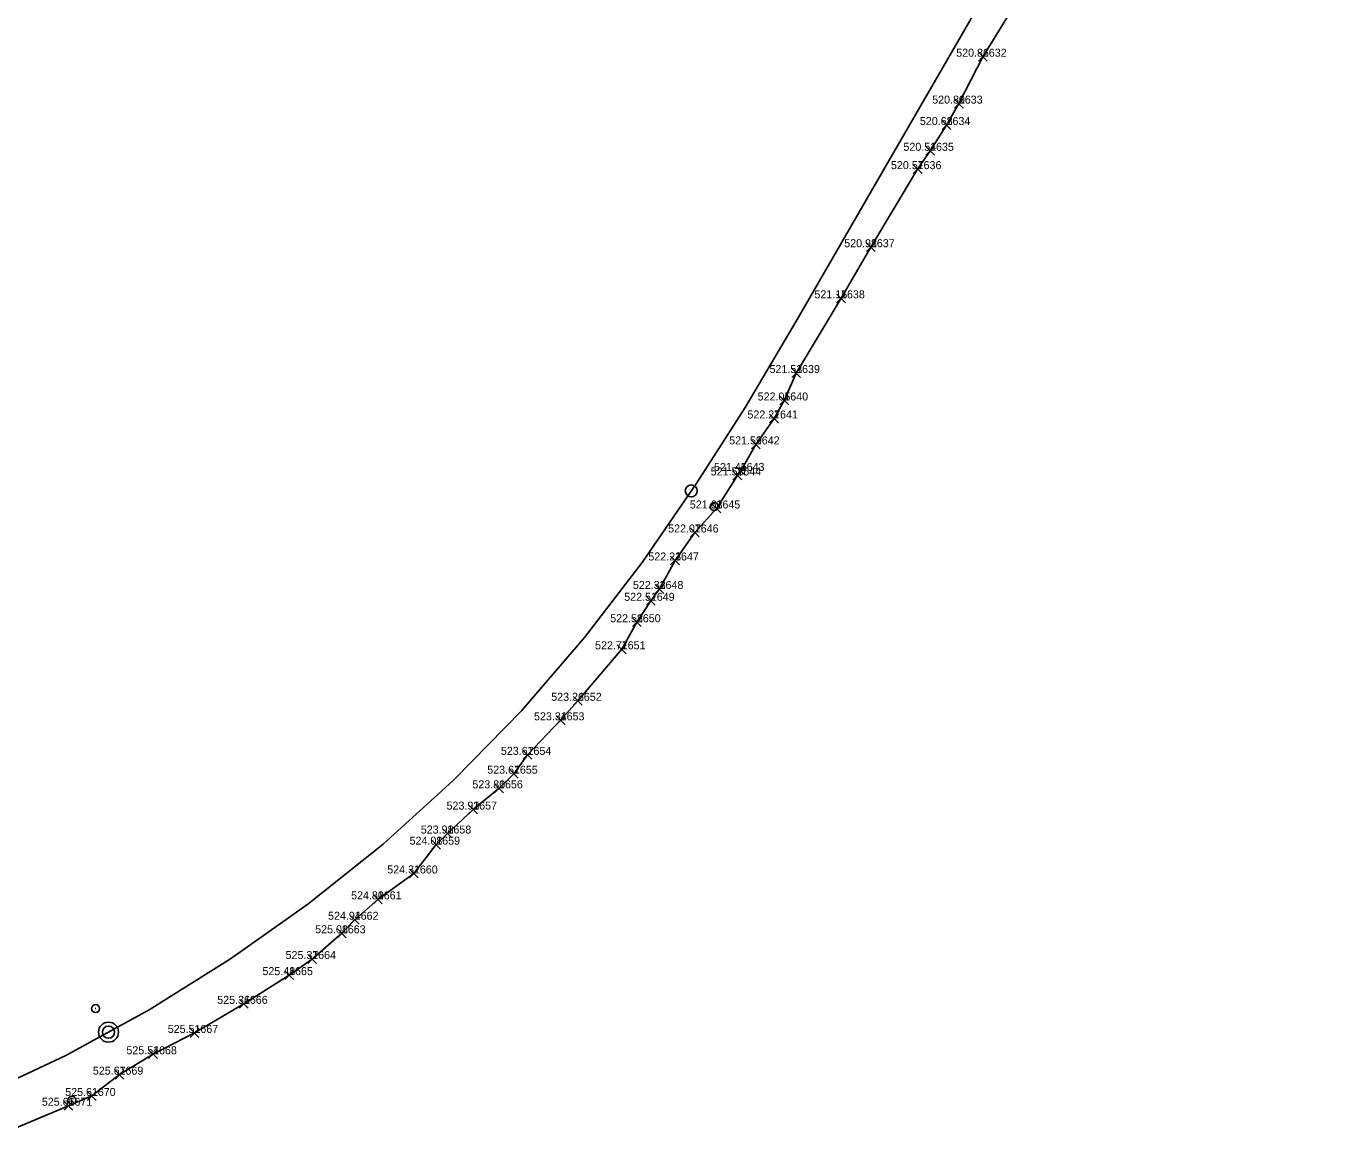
# Model space of a CAD drawing. Extents: x -874058 to -854960, y -10531873 to -1049126.
# Drawn here: x -873329.2 to -873165.2, y -1055553.5 to -1055414.3 of the extents above; entities that cross this region are included whole.
import ezdxf

# ---------------------------------------------------------------- set-up
doc = ezdxf.new("R2010")
doc.units = 0
for name, color, linetype in [('Vrstva 1', 7, 'Continuous'), ('Vrstva 32', 7, 'Continuous'), ('Vrstva 53', 7, 'Continuous'), ('Vrstva 60', 7, 'Continuous'), ('Vrstva 61', 7, 'Continuous'), ('Vrstva 7', 7, 'Continuous')]:
    doc.layers.add(name, color=color, linetype=linetype)

msp = doc.modelspace()

# ---------------------------------------------------------------- linework, layer by layer
at = {"layer": 'Vrstva 1'}
for points in [[(-873275.57, -1055508.36), (-873267.31, -1055499.92), (-873259.42, -1055490.74), (-873252.21, -1055481.36), (-873245.37, -1055471.4), (-873239.36, -1055461.98), (-873232.85, -1055450.97), (-873220.77, -1055430.09), (-873208.5, -1055408.85), (-873191.18, -1055379.14), (-873184.84, -1055368.35), (-873165.16, -1055339.14)], [(-873275.57, -1055508.36), (-873275.87, -1055508.66), (-873284.6, -1055516.56), (-873293.99, -1055524.06), (-873303.64, -1055530.92), (-873313.81, -1055537.27), (-873324.24, -1055542.99), (-873335.18, -1055548.1)]]:
    msp.add_lwpolyline(points, dxfattribs=at)
at = {"layer": 'Vrstva 32'}
for points in [[(-873172.75, -1055355.36), (-873174.08, -1055358.11), (-873177.47, -1055363.85), (-873180.92, -1055369.11), (-873185.51, -1055377.43), (-873189.85, -1055384.95), (-873191.55, -1055387.13), (-873194.09, -1055391.21), (-873195.62, -1055394.44), (-873196.65, -1055396.26), (-873200.6, -1055402.92), (-873201.9, -1055404.96), (-873203.17, -1055407.6), (-873209.64, -1055418.14), (-873212.64, -1055424), (-873214.18, -1055426.68), (-873216.23, -1055429.9), (-873217.79, -1055432.19), (-873223.63, -1055441.95), (-873227.36, -1055448.34), (-873232.97, -1055457.68)], [(-873232.97, -1055457.68), (-873234.45, -1055461.11), (-873235.73, -1055463.36), (-873238.01, -1055466.6), (-873239.9, -1055469.91), (-873240.32, -1055470.48), (-873242.93, -1055474.61), (-873245.64, -1055477.61), (-873248.11, -1055481.11), (-873250.04, -1055484.67), (-873251.13, -1055486.15), (-873252.88, -1055488.83), (-873254.77, -1055492.21), (-873260.25, -1055498.65), (-873262.4, -1055501.09), (-873266.54, -1055505.41), (-873268.24, -1055507.76), (-873270.1, -1055509.59), (-873273.33, -1055512.25), (-873276.55, -1055515.24), (-873277.95, -1055516.63), (-873280.74, -1055520.23), (-873285.26, -1055523.47), (-873288.14, -1055526.02), (-873289.75, -1055527.71), (-873293.45, -1055530.93), (-873296.34, -1055532.94), (-873301.99, -1055536.53), (-873308.17, -1055540.17), (-873313.34, -1055542.83), (-873317.53, -1055545.38), (-873320.99, -1055548.05), (-873323.91, -1055549.27), (-873334.09, -1055553.52)]]:
    msp.add_lwpolyline(points, dxfattribs=at)
at = {"layer": 'Vrstva 53'}
msp.add_line((-873323.53, -1055548.59), (-873323.43, -1055548.59), dxfattribs=at)
msp.add_circle((-873323.48, -1055548.59), 0.499, dxfattribs=at)
at = {"layer": 'Vrstva 60'}
for p, q in [((-873210.19, -1055418.69), (-873209.09, -1055417.59)), ((-873209.09, -1055418.69), (-873210.19, -1055417.59)), ((-873213.19, -1055424.55), (-873212.09, -1055423.45)), ((-873212.09, -1055424.55), (-873213.19, -1055423.45)), ((-873214.73, -1055427.23), (-873213.63, -1055426.13)), ((-873213.63, -1055427.23), (-873214.73, -1055426.13)), ((-873216.78, -1055430.45), (-873215.68, -1055429.35)), ((-873215.68, -1055430.45), (-873216.78, -1055429.35)), ((-873218.34, -1055432.74), (-873217.24, -1055431.64)), ((-873217.24, -1055432.74), (-873218.34, -1055431.64)), ((-873224.18, -1055442.5), (-873223.08, -1055441.4)), ((-873223.08, -1055442.5), (-873224.18, -1055441.4)), ((-873227.91, -1055448.89), (-873226.81, -1055447.79)), ((-873226.81, -1055448.89), (-873227.91, -1055447.79)), ((-873233.52, -1055458.23), (-873232.42, -1055457.13)), ((-873232.42, -1055458.23), (-873233.52, -1055457.13)), ((-873235, -1055461.66), (-873233.9, -1055460.56)), ((-873233.9, -1055461.66), (-873235, -1055460.56)), ((-873236.28, -1055463.91), (-873235.18, -1055462.81)), ((-873235.18, -1055463.91), (-873236.28, -1055462.81)), ((-873238.56, -1055467.15), (-873237.46, -1055466.05)), ((-873237.46, -1055467.15), (-873238.56, -1055466.05)), ((-873240.87, -1055471.03), (-873239.77, -1055469.93)), ((-873239.77, -1055471.03), (-873240.87, -1055469.93)), ((-873240.45, -1055470.46), (-873239.35, -1055469.36)), ((-873239.35, -1055470.46), (-873240.45, -1055469.36)), ((-873243.48, -1055475.16), (-873242.38, -1055474.06)), ((-873242.38, -1055475.16), (-873243.48, -1055474.06)), ((-873246.19, -1055478.16), (-873245.09, -1055477.06)), ((-873245.09, -1055478.16), (-873246.19, -1055477.06)), ((-873248.66, -1055481.66), (-873247.56, -1055480.56)), ((-873247.56, -1055481.66), (-873248.66, -1055480.56)), ((-873250.59, -1055485.22), (-873249.49, -1055484.12)), ((-873249.49, -1055485.22), (-873250.59, -1055484.12)), ((-873251.68, -1055486.7), (-873250.58, -1055485.6)), ((-873250.58, -1055486.7), (-873251.68, -1055485.6)), ((-873253.43, -1055489.38), (-873252.33, -1055488.28)), ((-873252.33, -1055489.38), (-873253.43, -1055488.28)), ((-873255.32, -1055492.76), (-873254.22, -1055491.66)), ((-873254.22, -1055492.76), (-873255.32, -1055491.66)), ((-873260.8, -1055499.2), (-873259.7, -1055498.1)), ((-873259.7, -1055499.2), (-873260.8, -1055498.1)), ((-873262.95, -1055501.64), (-873261.85, -1055500.54)), ((-873261.85, -1055501.64), (-873262.95, -1055500.54)), ((-873267.09, -1055505.96), (-873265.99, -1055504.86)), ((-873265.99, -1055505.96), (-873267.09, -1055504.86)), ((-873268.79, -1055508.31), (-873267.69, -1055507.21)), ((-873267.69, -1055508.31), (-873268.79, -1055507.21)), ((-873270.65, -1055510.14), (-873269.55, -1055509.04)), ((-873269.55, -1055510.14), (-873270.65, -1055509.04)), ((-873273.88, -1055512.8), (-873272.78, -1055511.7)), ((-873272.78, -1055512.8), (-873273.88, -1055511.7)), ((-873278.5, -1055517.18), (-873277.4, -1055516.08)), ((-873277.4, -1055517.18), (-873278.5, -1055516.08)), ((-873277.1, -1055515.79), (-873276, -1055514.69)), ((-873276, -1055515.79), (-873277.1, -1055514.69)), ((-873281.29, -1055520.78), (-873280.19, -1055519.68)), ((-873280.19, -1055520.78), (-873281.29, -1055519.68)), ((-873285.81, -1055524.02), (-873284.71, -1055522.92)), ((-873284.71, -1055524.02), (-873285.81, -1055522.92)), ((-873288.69, -1055526.57), (-873287.59, -1055525.47)), ((-873287.59, -1055526.57), (-873288.69, -1055525.47)), ((-873290.3, -1055528.26), (-873289.2, -1055527.16)), ((-873289.2, -1055528.26), (-873290.3, -1055527.16)), ((-873294, -1055531.48), (-873292.9, -1055530.38)), ((-873292.9, -1055531.48), (-873294, -1055530.38)), ((-873296.89, -1055533.49), (-873295.79, -1055532.39)), ((-873295.79, -1055533.49), (-873296.89, -1055532.39)), ((-873302.54, -1055537.08), (-873301.44, -1055535.98)), ((-873301.44, -1055537.08), (-873302.54, -1055535.98)), ((-873308.72, -1055540.72), (-873307.62, -1055539.62)), ((-873307.62, -1055540.72), (-873308.72, -1055539.62)), ((-873313.89, -1055543.38), (-873312.79, -1055542.28)), ((-873312.79, -1055543.38), (-873313.89, -1055542.28)), ((-873318.08, -1055545.93), (-873316.98, -1055544.83)), ((-873316.98, -1055545.93), (-873318.08, -1055544.83)), ((-873324.46, -1055549.82), (-873323.36, -1055548.72)), ((-873323.36, -1055549.82), (-873324.46, -1055548.72)), ((-873321.54, -1055548.6), (-873320.44, -1055547.5)), ((-873320.44, -1055548.6), (-873321.54, -1055547.5))]:
    msp.add_line(p, q, dxfattribs=at)
at = {"layer": 'Vrstva 7'}
for p, q in [((-873243.25, -1055474.38), (-873243.15, -1055474.38)), ((-873320.57, -1055537.13), (-873320.47, -1055537.13))]:
    msp.add_line(p, q, dxfattribs=at)
for centre, radius in [((-873246.07, -1055472.41), 0.75), ((-873243.2, -1055474.38), 0.5), ((-873320.52, -1055537.13), 0.5), ((-873318.91, -1055540.07), 1.25), ((-873318.91, -1055540.07), 0.752)]:
    msp.add_circle(centre, radius, dxfattribs=at)

# ---------------------------------------------------------------- texts
at = {"layer": 'Vrstva 60'}
for s, p in [('1632', (-873209.64, -1055418.14)), ('1633', (-873212.64, -1055424)), ('1634', (-873214.18, -1055426.68)), ('1635', (-873216.23, -1055429.9)), ('1636', (-873217.79, -1055432.19)), ('1637', (-873223.63, -1055441.95)), ('1638', (-873227.36, -1055448.34)), ('1639', (-873232.97, -1055457.68)), ('1640', (-873234.45, -1055461.11)), ('1641', (-873235.73, -1055463.36)), ('1642', (-873238.01, -1055466.6)), ('1644', (-873240.32, -1055470.48)), ('1643', (-873239.9, -1055469.91)), ('1645', (-873242.93, -1055474.61)), ('1646', (-873245.64, -1055477.61)), ('1647', (-873248.11, -1055481.11)), ('1648', (-873250.04, -1055484.67)), ('1649', (-873251.13, -1055486.15)), ('1650', (-873252.88, -1055488.83)), ('1651', (-873254.77, -1055492.21)), ('1652', (-873260.25, -1055498.65)), ('1653', (-873262.4, -1055501.09)), ('1654', (-873266.54, -1055505.41)), ('1655', (-873268.24, -1055507.76)), ('1656', (-873270.1, -1055509.59)), ('1657', (-873273.33, -1055512.25)), ('1658', (-873276.55, -1055515.24)), ('1659', (-873277.95, -1055516.63)), ('1660', (-873280.74, -1055520.23)), ('1661', (-873285.26, -1055523.47)), ('1662', (-873288.14, -1055526.02)), ('1663', (-873289.75, -1055527.71)), ('1664', (-873293.45, -1055530.93)), ('1665', (-873296.34, -1055532.94)), ('1666', (-873301.99, -1055536.53)), ('1667', (-873308.17, -1055540.17)), ('1668', (-873313.34, -1055542.83)), ('1669', (-873317.53, -1055545.38)), ('1670', (-873320.99, -1055548.05)), ('1671', (-873323.91, -1055549.27))]:
    msp.add_text(s, height=1, dxfattribs=at).set_placement(p)
at = {"layer": 'Vrstva 61'}
for s, p in [('520.86 ', (-873212.97, -1055418.14)), ('520.80 ', (-873215.97, -1055424)), ('520.68 ', (-873217.51, -1055426.68)), ('520.54 ', (-873219.56, -1055429.9)), ('520.57 ', (-873221.12, -1055432.19)), ('520.98 ', (-873226.96, -1055441.95)), ('521.15 ', (-873230.69, -1055448.34)), ('521.53 ', (-873236.3, -1055457.68)), ('522.05 ', (-873237.78, -1055461.11)), ('522.27 ', (-873239.06, -1055463.36)), ('521.59 ', (-873241.34, -1055466.6)), ('521.58 ', (-873243.65, -1055470.48)), ('521.45 ', (-873243.23, -1055469.91)), ('521.63 ', (-873246.26, -1055474.61)), ('522.07 ', (-873248.97, -1055477.61)), ('522.23 ', (-873251.44, -1055481.11)), ('522.33 ', (-873253.37, -1055484.67)), ('522.51 ', (-873254.46, -1055486.15)), ('522.58 ', (-873256.21, -1055488.83)), ('522.77 ', (-873258.1, -1055492.21)), ('523.26 ', (-873263.58, -1055498.65)), ('523.34 ', (-873265.73, -1055501.09)), ('523.67 ', (-873269.87, -1055505.41)), ('523.67 ', (-873271.57, -1055507.76)), ('523.80 ', (-873273.43, -1055509.59)), ('523.93 ', (-873276.66, -1055512.25)), ('523.98 ', (-873279.88, -1055515.24)), ('524.08 ', (-873281.28, -1055516.63)), ('524.31 ', (-873284.07, -1055520.23)), ('524.80 ', (-873288.59, -1055523.47)), ('524.94 ', (-873291.47, -1055526.02)), ('525.08 ', (-873293.08, -1055527.71)), ('525.37 ', (-873296.78, -1055530.93)), ('525.48 ', (-873299.67, -1055532.94)), ('525.36 ', (-873305.32, -1055536.53)), ('525.51 ', (-873311.5, -1055540.17)), ('525.54 ', (-873316.67, -1055542.83)), ('525.67 ', (-873320.86, -1055545.38)), ('525.61 ', (-873324.32, -1055548.05)), ('525.66 ', (-873327.24, -1055549.27))]:
    msp.add_text(s, height=1, dxfattribs=at).set_placement(p)

doc.saveas('drawing.dxf')
